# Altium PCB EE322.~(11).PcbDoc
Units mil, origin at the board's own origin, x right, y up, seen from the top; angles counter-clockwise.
Board outline 6000 x 4000 mil, 2 copper layers (Top Layer, Bottom Layer); 26 components, 15 nets, 57 pads, 0 vias.
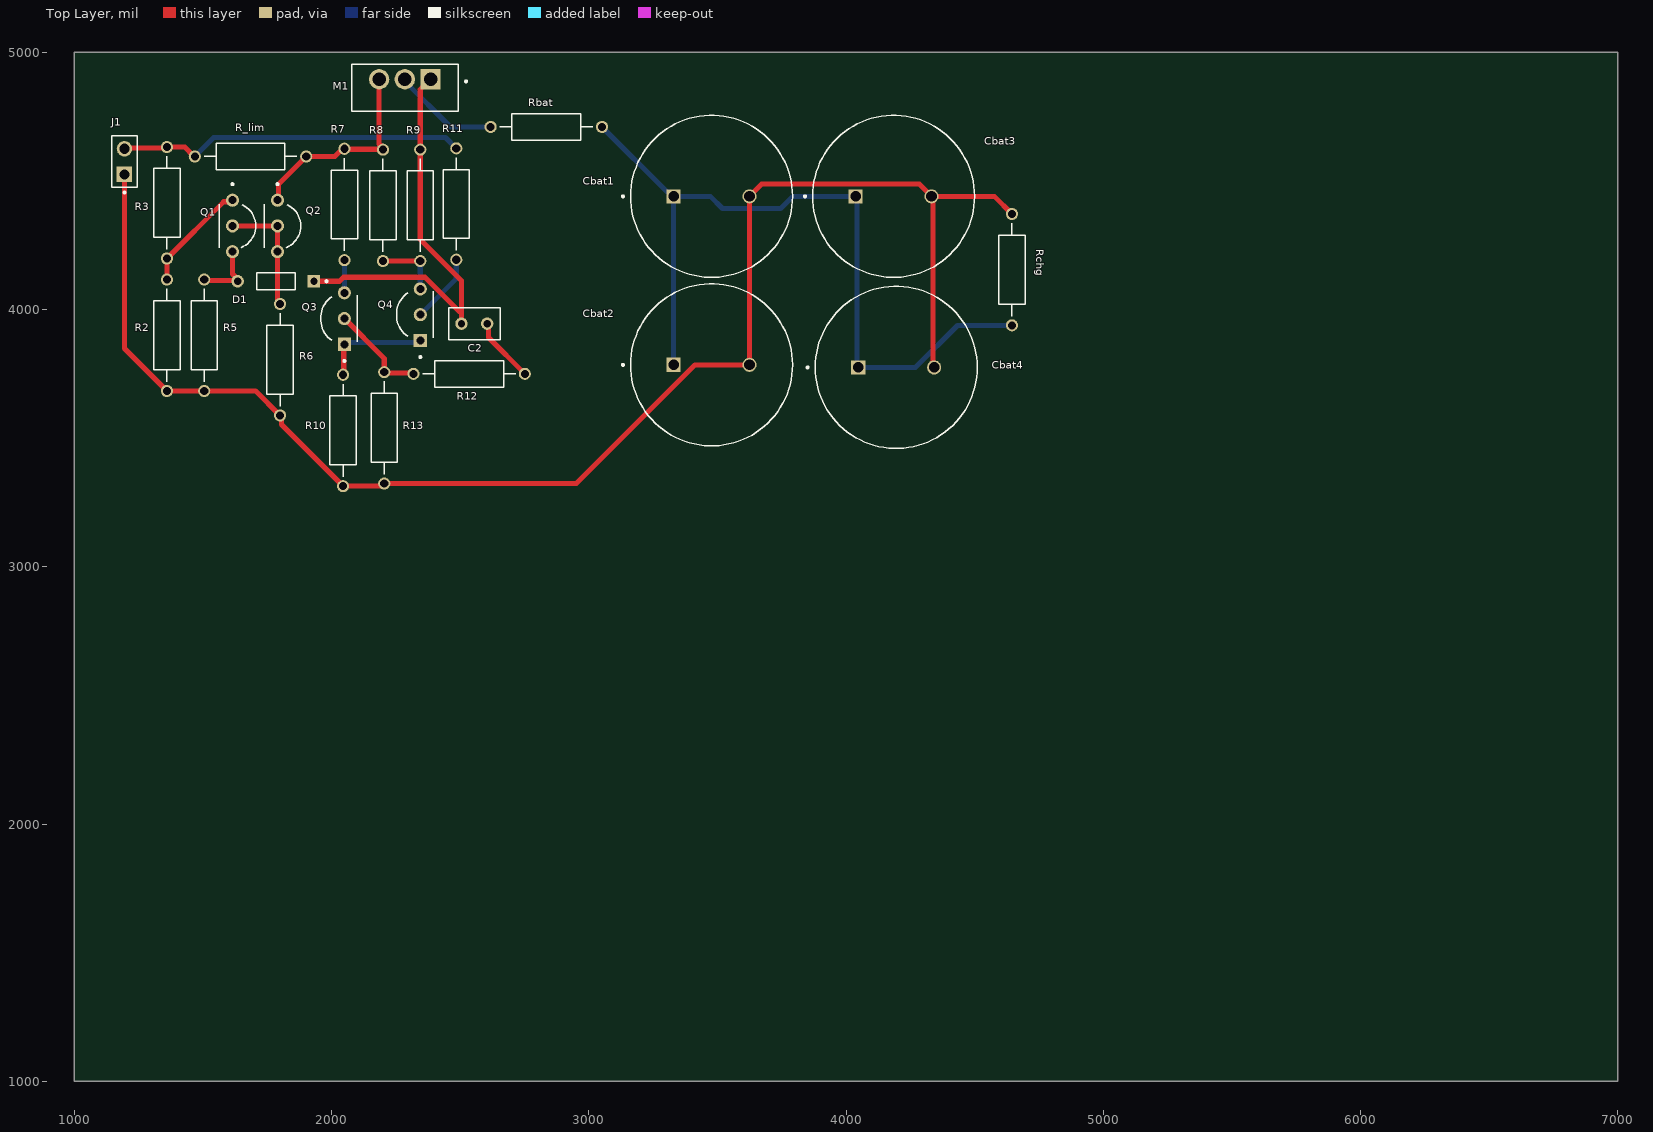
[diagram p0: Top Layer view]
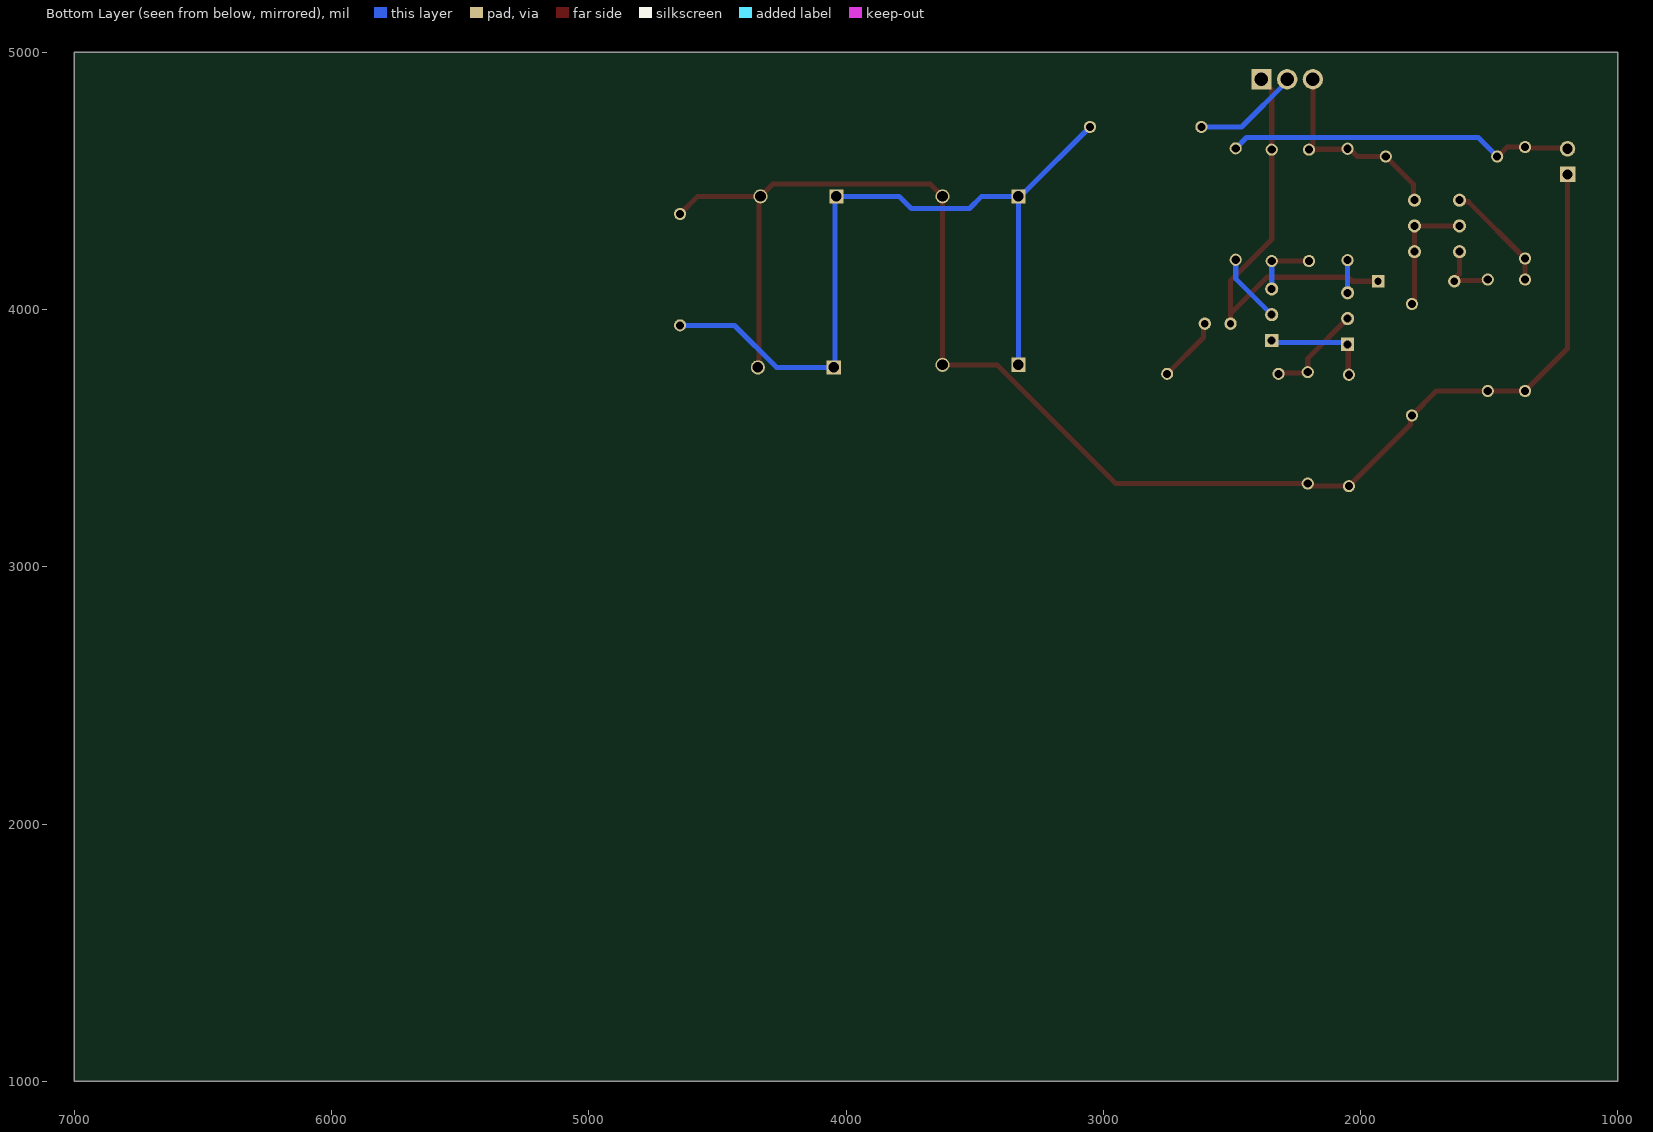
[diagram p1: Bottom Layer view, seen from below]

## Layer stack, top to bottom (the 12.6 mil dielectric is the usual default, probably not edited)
Top Solder: solder mask 0.4, Solder Resist, Dk 3.5
Top Layer: signal copper 1.4
Dielectric 1: dielectric 12.6, FR-4, Dk 4.8
Bottom Layer: signal copper 1.4
Bottom Solder: solder mask 0.4, Solder Resist, Dk 3.5

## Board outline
1000,1000 7000,1000 7000,5000 1000,5000

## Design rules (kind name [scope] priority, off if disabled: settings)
Clearance [All] p1: gap=10 ignorepadtopadclearanceinfootprint=FALSE
Height [All] p1: minheight=0 maxheight=1500 prefheight=500
PolygonConnect [All] p1: connectstyle=Relief reliefconductorwidth=10 reliefentries=4 polygonreliefangle="90 Angle" airgapwidth=10
RoutingVias [All] p1: holewidth=28 width=50 viastyle="Through Hole" minholewidth=28 minwidth=50 maxholewidth=28 maxwidth=50
SilkToSolderMaskClearance [IsPad] p1: minsilkscreentomaskgap=9 clearancetoexposedcopper=TRUE
SolderMaskExpansion [All] p1: expansion=0 istentingtop=FALSE
Width [All] p1: maxlimit=40 minlimit=20 preferedwidth=20
28 further rules are at their usual default settings.

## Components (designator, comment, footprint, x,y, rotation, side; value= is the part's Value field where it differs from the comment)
C2 "SR291C104KAR" CAPRR254W50L508T317H508 2555,3945 r0 top
Cbat1 "ECA1HHG222" CAPPRD750W80D1600H3150 3477.36,4440 r0 top
Cbat2 "ECA1HHG222" CAPPRD750W80D1600H3150 3477.36,3785 r0 top
Cbat3 "ECA1HHG222" CAPPRD750W80D1600H3150 4185,4440 r0 top
Cbat4 "ECA1HHG222" CAPPRD750W80D1600H3150 4195,3775 r0 top
D1 "1N4148" DIOAD753W49L380D172B 1783.37,4110 r180 top
J1 "DS1021-1X2SF11-B" CONNFLY_DS1021-1X2SF11-B 1195,4575 r90 top
M1 "IRF9540" TO254P1052X465X1989-3 2385,4895 r180 top
Q1 "2N3906" TO92254P460H750-3#1 1615,4325 r270 top
Q2 "2N3906" TO92254P460H750-3#1 1790,4325 r270 top
Q3 "2N3904" TO92254P460H750-3#2 2050,3965 r90 top
Q4 "2N3904" TO92254P460H750-3#2 2345,3980 r90 top
R2 "MFR-25FBF52-10K" RESAD1100W55L680D260 1360,3900 r90 top
R3 "MFR-25FBF52-10K" RESAD1100W55L680D260 1360,4415 r90 top
R5 "MFR-25FBF52-10K" RESAD1100W55L680D260 1505,3900 r90 top
R6 "MFR-25FBF52-10K" RESAD1100W55L680D260 1800,3805 r90 top
R7 "MFR-25FBF52-10K" RESAD1100W55L680D260 2050,4408.46 r90 top
R8 "MFR-25FBF52-10K" RESAD1100W55L680D260 2200,4405 r90 top
R9 "MFR-25FBF52-10K" RESAD1100W55L680D260 2345,4405 r90 top
R10 "MFR-25FBF52-10K" RESAD1100W55L680D260 2045,3530 r90 top
R11 "MFR-25FBF52-10K" RESAD1100W55L680D260 2485,4410 r90 top
R12 "MFR-25FBF52-10K" RESAD1100W55L680D260 2535,3750 r0 top
R13 "MFR-25FBF52-10K" RESAD1100W55L680D260 2205,3540 r90 top
R_lim "MFR-25FBF52-10K" RESAD1100W55L680D260 1685,4595 r0 top
Rbat "MFR-25FBF52-10K" RESAD1100W55L680D260 2835,4710 r180 top
Rchg "MFR-25FBF52-10K" RESAD1100W55L680D260 4645,4155 r270 top

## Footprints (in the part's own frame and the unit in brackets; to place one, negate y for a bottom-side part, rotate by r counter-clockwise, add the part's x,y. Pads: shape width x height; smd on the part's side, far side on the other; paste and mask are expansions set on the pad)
CAPPRD750W80D1600H3150 [mm]
  round 1.4 hole 1.05: N(3.75,0)
  rect 1.4x1.4 hole 1.05: P(-3.75,0)
  silkscreen extent -8.85,-8 8,8, body extent -8,-8 8,8, height 31.5
CAPRR254W50L508T317H508 [mm]
  round 1.218 hole 0.71: 1(-1.27,0) 2(1.27,0)
  silkscreen extent -2.54,-1.59 2.54,1.59
CONNFLY_DS1021-1X2SF11-B [mm]
  rect 1.53x1.53 / inner round 1.53 / far side rect 1.53x1.53 hole 1.02 mask+0.102: 1(-1.27,0)
  round 1.53 hole 1.02 mask+0.102: 2(1.27,0)
  silkscreen extent -3.15,-1.25 2.54,1.25, body extent -2.54,-1.25 2.54,1.25, height 8.6
DIOAD753W49L380D172B [mm]
  round 1.238 hole 0.73 mask+0.102: A(3.768,0)
  rect 1.238x1.238 / inner round 1.238 / far side rect 1.238x1.238 hole 0.73 mask+0.102: K(-3.768,0)
  silkscreen extent -5.1,-0.86 1.9,0.86
RESAD1100W55L680D260 [mm]
  round 1.2 hole 0.8: 1(-5.5,0) 2(5.5,0)
  silkscreen extent -4.58,-1.3 4.58,1.3, body extent -5.77,-1.2 5.77,1.2, height 2.4
TO254P1052X465X1989-3 [mm]
  rect 2.01x2.01 / inner round 2.01 / far side rect 2.01x2.01 hole 1.34: 1(0,0)
  round 2.01 hole 1.34: 2(2.54,0) 3(5.08,0)
  silkscreen extent -3.6,-1.5 7.8,3.16, body extent -5.12,-1.54 5.12,2.91, height 19.89
TO92254P460H750-3#1 [mm]
  round 1.298 hole 0.79 mask+0.102: 1(-2.54,0) 2(0,0) 3(2.54,0)
  silkscreen extent -4.22,-1.3 2.15,2.3, body extent -2.74,-1.27 2.74,2.33, height 8.09
TO92254P460H750-3#2 [mm]
  rect 1.298x1.298 / inner round 1.298 / far side rect 1.298x1.298 hole 0.79 mask+0.102: 1(-2.54,0)
  round 1.298 hole 0.79 mask+0.102: 2(0,0) 3(2.54,0)
  silkscreen extent -4.29,-1.27 2.3,2.33, body extent -2.74,-1.27 2.74,2.33, height 8.09

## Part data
C2: "SR Series 5.08 x 5.08 mm 100 nF 100 V Â±10 % Tol. X7R Radial Lead/SkyCapÂ®", Package=None
Cbat1 Cbat2 Cbat3 Cbat4: "Cap Aluminum 2200uF 50V 20% (16 X 31.5mm) Radial Aluminum Cylindrical Can 7.5mm 1470mA 2000 hr 105C Bulk", Package="RADIAL-2 Panasonic"
D1: "Diode Standard 75V 200mA Surface Mount SOD-523F", Package="AXIAL LEAD-2 ON Semiconductor"
J1: "2 position 2.54mm single row vertical pin header", Package=None
M1: "P-Channel 100 V 19A (Tc) 3.7W (Ta), 150W (Tc) Surface Mount DÂ²PAK (TO-263)", Package="TO-220-3 Vishay"
Q1 Q2: "BJT, TO-92, 40V, 200mA, PNP, 0.625W, 150Â°C", Package="TO-92 Diotec"
Q3 Q4: "BJT, TO-92, 40V, 200mA, NPN, 0.625W, 150Â°C", Package="TO-92 Diotec"
R2 R3 R5 R6 R7 R8 R9 R10 R11 R12 R13 R_lim Rbat Rchg: "10.2 kOhms Â±1% 0.25W, 1/4W Through Hole Resistor Axial - Metal Film", Package="RADIAL-2 YAGEO"

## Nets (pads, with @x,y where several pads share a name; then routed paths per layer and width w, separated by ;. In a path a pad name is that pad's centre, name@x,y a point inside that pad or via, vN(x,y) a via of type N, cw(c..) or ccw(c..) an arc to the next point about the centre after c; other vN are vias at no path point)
gnd: Cbat1.N Cbat2.N Cbat3.N Cbat4.N J1.1 R2.1 R5.1 R6.1 R10.1 R13.1 Rchg.1 | length 5952.9
  Top Layer w20: J1.1 1195,3848.46 R2.1 R5.1 1705,3683.46 R6.1 1805.21,3583.25 1805.21,3553.25 R10.1 2187.63,3313.46 2197.63,3323.46 R13.1 2951.59,3323.46 3413.13,3785 Cbat2.N Cbat1.N 3672.56,4487.56 4285.08,4487.56 Cbat3.N ; Cbat4.N 4337.64,3780 4337.64,4435 Cbat3.N ; Rchg.1 4576.54,4440 Cbat3.N
NetC2_1: C2.1 D1.K M1.1 R9.2 | length 1663.4
  Top Layer w20: D1.K 2030.58,4110 2046.13,4125.55 2363.87,4125.55 2499.65,3989.77 ; M1.1 2345,4855 R9.2 2345,4271.77 2505,4111.77 C2.1
NetC2_2: C2.2 R12.2 | length 255.7
  Top Layer w20: C2.2 2610.35,3939.65 2610.35,3891.19 R12.2
NetCbat1_P: Cbat1.P Cbat2.P Cbat3.P Cbat4.P Rbat.1 Rchg.2 | length 3126.6
  Bottom Layer w20: Rbat.1 3303.98,4457.56 3312.17,4457.56 Cbat1.P ; Cbat2.P Cbat1.P ; Rchg.2 4433.01,3938.46 4269.54,3775 Cbat4.P 4042.36,3780 4042.36,4435 Cbat3.P 3793.57,4440 3746.01,4392.44 3519.77,4392.44 3472.21,4440 Cbat1.P
NetD1_A: D1.A Q1.3 R5.2 | length 256
  Top Layer w20: R5.2 1508.27,4113.27 1631.73,4113.27 D1.A 1635,4117.78 1615,4137.78 Q1.3
NetM1_3: M1.3 Q2.1 R7.2 R8.2 R_lim.2 | length 808.2
  Top Layer w20: Q2.1 1794.46,4429.46 1794.46,4487.92 R_lim.2 2012.63,4595 2042.63,4625 R7.2 2051.73,4623.27 2198.27,4623.27 R8.2 2200,4628.91 2185,4643.91 M1.3
NetQ1_1: Q1.1 R2.2 R3.1 | length 430.8
  Top Layer w20: R2.2 R3.1 1580.58,4419.05 1609.05,4419.05 Q1.1
NetQ1_2: Q1.2 Q2.2 Q2.3 R6.2 | length 482.6
  Top Layer w20: Q1.2 Q2.2 Q2.3 1790,4038.91 1800,4028.91 R6.2
NetQ3_1: Q3.1 Q4.1 R10.2 | length 421.7
  Top Layer w20: R10.2 2047.5,3749.04 2047.5,3862.5 Q3.1
  Bottom Layer w20: Q3.1 2057.5,3872.5 2337.5,3872.5 Q4.1
NetQ3_2: Q3.2 R12.1 R13.2 | length 388.8
  Top Layer w20: Q3.2 2204.84,3810.16 2204.84,3756.69 R13.2 2208.27,3753.27 2315.2,3753.27 R12.1
NetQ3_3: Q3.3 R7.1 | length 126.9
  Bottom Layer w20: Q3.3 R7.1
NetQ4_2: Q4.2 R11.1 | length 271.5
  Bottom Layer w20: Q4.2 2485,4120 R11.1
NetQ4_3: Q4.3 R8.1 R9.1 | length 253.5
  Top Layer w20: R8.1 R9.1
  Bottom Layer w20: Q4.3 R9.1
VBat: M1.2 Rbat.2 | length 414.4
  Bottom Layer w20: M1.2 2285,4887.58 2462.58,4710 Rbat.2
vdd: J1.2 R3.2 R11.2 R_lim.1 | length 1355.8
  Top Layer w20: J1.2 1198.27,4628.27 1356.73,4628.27 R3.2 1429.17,4631.54 1465.7,4595 R_lim.1
  Bottom Layer w20: R_lim.1 1542.09,4668.62 2442.91,4668.62 R11.2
